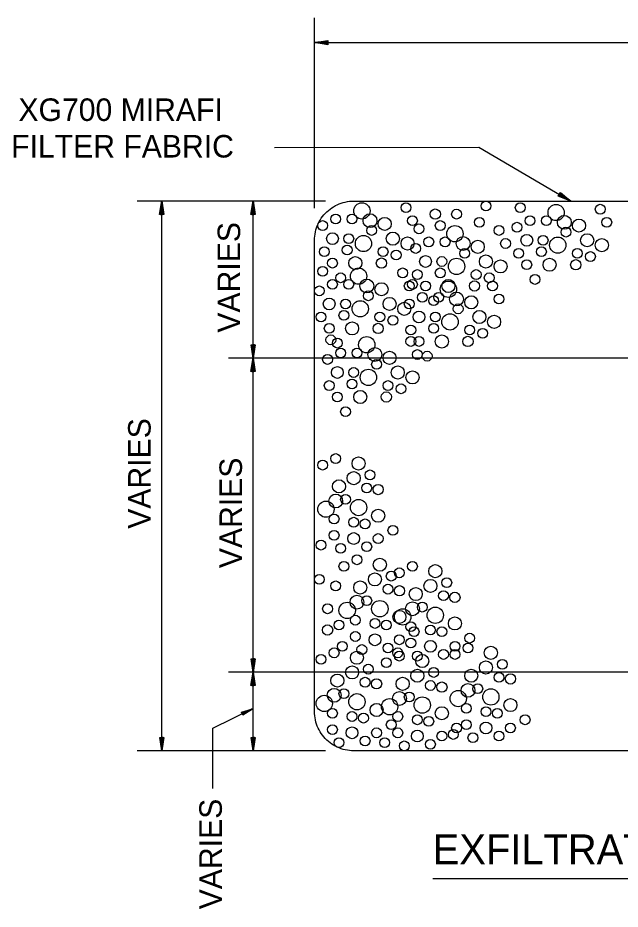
# Model space of a CAD drawing. Extents: x -7.1 to 10, y -5 to 6.
# Drawn here: x 3.602 to 5.369, y -2.41 to 0.206 of the extents above; entities that cross this region are included whole.
import ezdxf

# ---------------------------------------------------------------- set-up
doc = ezdxf.new("R2010")
doc.units = 0
doc.layers.add('Level 11', color=7, linetype='Continuous')
doc.layers.add('Level 6', color=7, linetype='Continuous')

msp = doc.modelspace()

# ---------------------------------------------------------------- linework, layer by layer
at = {"layer": 'Level 11'}
for p, q in [((4.4721, -0.3523), (4.4721, 0.2058)), ((4.4721, 0.1333), (7.2371, 0.1333)), ((4.5041, -0.3319), (3.9515, -0.3319)), ((4.0241, -1.9448), (4.0241, -0.3319)), ((4.292, -0.7927), (4.292, -0.3319)), ((5.6597, -0.7927), (4.2194, -0.7927)), ((4.292, -1.7144), (4.292, -0.7927)), ((5.6597, -1.7144), (4.2194, -1.7144)), ((4.292, -1.9448), (4.292, -1.7144)), ((4.5041, -1.9448), (3.9515, -1.9448)), ((4.8194, -2.3197), (6.9886, -2.3197))]:
    msp.add_line(p, q, dxfattribs=at)
for points in [[(4.3544, -0.1742), (4.9543, -0.1734), (5.2241, -0.3319)], [(4.4748, -0.4223), (4.4763, -0.4163), (4.4781, -0.4103), (4.4803, -0.4045), (4.4827, -0.3987), (4.4855, -0.3931), (4.4886, -0.3877), (4.4919, -0.3824), (4.4956, -0.3774), (4.4995, -0.3725), (4.5036, -0.3679), (4.5081, -0.3635), (4.5127, -0.3593), (4.5176, -0.3554), (4.5226, -0.3518), (4.5279, -0.3484), (4.5333, -0.3453), (4.5389, -0.3425), (4.5446, -0.3401), (4.5505, -0.3379), (4.5565, -0.3361), (4.5625, -0.3346), (4.5686, -0.3334), (4.5748, -0.3326), (4.5811, -0.3321), (4.5873, -0.3319), (4.5873, -0.3319), (6.085, -0.3319)], [(7.1219, -1.9448), (4.5873, -1.9448), (4.5811, -1.9446), (4.5748, -1.9441), (4.5686, -1.9433), (4.5625, -1.9421), (4.5565, -1.9406), (4.5505, -1.9388), (4.5446, -1.9366), (4.5389, -1.9342), (4.5333, -1.9314), (4.5279, -1.9283), (4.5226, -1.925), (4.5176, -1.9213), (4.5127, -1.9174), (4.5081, -1.9133), (4.5036, -1.9088), (4.4995, -1.9042), (4.4956, -1.8993), (4.4919, -1.8943), (4.4886, -1.889), (4.4855, -1.8836), (4.4827, -1.878), (4.4803, -1.8723), (4.4781, -1.8664), (4.4763, -1.8604), (4.4748, -1.8544), (4.4736, -1.8482), (4.4728, -1.8421), (4.4722, -1.8358), (4.4721, -1.8296), (4.4721, -1.8296), (4.4721, -0.4471), (4.4723, -0.4409), (4.4728, -0.4346), (4.4736, -0.4285), (4.4748, -0.4223)], [(4.1735, -2.0552), (4.1736, -1.8784), (4.2894, -1.8219)]]:
    msp.add_lwpolyline(points, dxfattribs=at)
for centre, radius in [((4.611, -0.3606), 0.0239), ((4.7403, -0.3511), 0.0144), ((4.975, -0.3463), 0.0144), ((5.0756, -0.3511), 0.0144), ((4.8265, -0.3702), 0.0151), ((4.8888, -0.3702), 0.0144), ((5.181, -0.3654), 0.0239), ((5.3103, -0.3558), 0.0144), ((4.496, -0.4037), 0.0144), ((4.5343, -0.3846), 0.0144), ((4.5822, -0.3846), 0.0144), ((4.6349, -0.3894), 0.0203), ((4.678, -0.399), 0.0192), ((4.7595, -0.3894), 0.0144), ((4.8409, -0.4037), 0.0144), ((4.9559, -0.3942), 0.0144), ((5.1043, -0.3894), 0.0144), ((5.1522, -0.3894), 0.0144), ((5.2049, -0.3942), 0.0203), ((5.248, -0.4037), 0.0192), ((5.3295, -0.3942), 0.0144), ((4.6397, -0.4181), 0.0144), ((4.7786, -0.4133), 0.0144), ((4.884, -0.4277), 0.024), ((5.0133, -0.4181), 0.0144), ((5.066, -0.4085), 0.0144), ((5.2097, -0.4229), 0.0144), ((4.5248, -0.4421), 0.0173), ((4.5727, -0.4421), 0.0144), ((4.6158, -0.4564), 0.0239), ((4.702, -0.4421), 0.0192), ((4.7451, -0.4564), 0.0192), ((4.8074, -0.4516), 0.0144), ((4.8553, -0.4516), 0.0144), ((4.908, -0.4564), 0.0203), ((5.0325, -0.4564), 0.0144), ((5.0948, -0.4469), 0.0173), ((5.1427, -0.4469), 0.0144), ((5.1858, -0.4612), 0.0239), ((5.272, -0.4469), 0.0192), ((5.3151, -0.4612), 0.0192), ((4.5008, -0.4804), 0.0144), ((4.5679, -0.4756), 0.0144), ((4.6733, -0.4804), 0.0144), ((4.7691, -0.4708), 0.0144), ((4.9511, -0.466), 0.0192), ((5.1379, -0.4804), 0.0144), ((4.5918, -0.5139), 0.0192), ((4.7116, -0.49), 0.0144), ((4.7978, -0.5091), 0.0173), ((4.8457, -0.5091), 0.0144), ((4.9128, -0.4852), 0.0144), ((4.975, -0.5091), 0.0192), ((5.0708, -0.4852), 0.0144), ((5.2433, -0.4852), 0.0144), ((5.2816, -0.4947), 0.0144), ((4.5248, -0.5139), 0.0144), ((4.6685, -0.5139), 0.0151), ((4.8888, -0.5235), 0.024), ((5.0181, -0.5235), 0.0192), ((5.0948, -0.5187), 0.0144), ((5.1618, -0.5187), 0.0192), ((5.2385, -0.5187), 0.0151), ((4.496, -0.5379), 0.0144), ((4.5487, -0.557), 0.0144), ((4.6014, -0.5522), 0.0239), ((4.7307, -0.5426), 0.0144), ((4.7738, -0.5474), 0.0144), ((4.8409, -0.5426), 0.0144), ((4.9463, -0.5474), 0.0144), ((4.9846, -0.557), 0.0144), ((5.1187, -0.5618), 0.0144), ((4.5248, -0.5762), 0.0144), ((4.5727, -0.5762), 0.0144), ((4.6254, -0.581), 0.0203), ((4.6685, -0.5905), 0.0192), ((4.7499, -0.581), 0.0144), ((4.7595, -0.5762), 0.0144), ((4.7978, -0.581), 0.0144), ((4.8649, -0.5905), 0.024), ((4.8649, -0.581), 0.0192), ((4.9415, -0.581), 0.0151), ((4.9942, -0.581), 0.0144), ((4.4865, -0.5953), 0.0144), ((4.6301, -0.6097), 0.0144), ((4.7882, -0.6145), 0.0144), ((4.8361, -0.6145), 0.0144), ((4.8888, -0.6193), 0.0203), ((4.5152, -0.6337), 0.0173), ((4.5631, -0.6337), 0.0144), ((4.6062, -0.648), 0.0239), ((4.6924, -0.6337), 0.0192), ((4.7499, -0.6337), 0.0144), ((4.8217, -0.6241), 0.0144), ((4.9319, -0.6289), 0.0192), ((5.0133, -0.6193), 0.0144), ((4.5583, -0.6672), 0.0144), ((4.7355, -0.648), 0.0192), ((4.8936, -0.648), 0.0144), ((4.9559, -0.672), 0.0192), ((4.4912, -0.672), 0.0144), ((4.6637, -0.672), 0.0144), ((4.702, -0.6816), 0.0144), ((4.7786, -0.672), 0.0173), ((4.8265, -0.672), 0.0144), ((4.8696, -0.6863), 0.024), ((4.999, -0.6863), 0.0192), ((4.5152, -0.7055), 0.0144), ((4.5822, -0.7055), 0.0192), ((4.6589, -0.7055), 0.0151), ((4.7547, -0.7103), 0.0144), ((4.8217, -0.7055), 0.0144), ((4.9271, -0.7103), 0.0144), ((4.9654, -0.7199), 0.0144), ((4.52, -0.739), 0.0144), ((4.6254, -0.7534), 0.0239), ((4.7547, -0.7438), 0.0144), ((4.7786, -0.7438), 0.0144), ((4.8457, -0.7438), 0.0192), ((4.9223, -0.7438), 0.0151), ((4.5391, -0.7486), 0.0144), ((4.5104, -0.7965), 0.0144), ((4.5487, -0.7774), 0.0144), ((4.5966, -0.7774), 0.0144), ((4.6493, -0.7821), 0.0203), ((4.6924, -0.7917), 0.0192), ((4.7738, -0.7821), 0.0144), ((4.8026, -0.7869), 0.0144), ((4.6541, -0.8109), 0.0144), ((4.5391, -0.8348), 0.0173), ((4.587, -0.8348), 0.0144), ((4.6301, -0.8492), 0.0239), ((4.7164, -0.8348), 0.0192), ((4.7595, -0.8492), 0.0192), ((4.5152, -0.8731), 0.0144), ((4.5822, -0.8684), 0.0144), ((4.6876, -0.8731), 0.0144), ((4.6062, -0.9067), 0.0192), ((4.7259, -0.8827), 0.0144), ((4.5391, -0.9067), 0.0144), ((4.6828, -0.9067), 0.0151), ((4.5631, -0.9498), 0.0144), ((4.496, -1.1066), 0.0144), ((4.5343, -1.0874), 0.0144), ((4.6014, -1.1018), 0.0192), ((4.6349, -1.1353), 0.0144), ((4.5439, -1.1689), 0.0192), ((4.587, -1.1449), 0.0192), ((4.6254, -1.1736), 0.0144), ((4.6589, -1.1784), 0.0151), ((4.5343, -1.212), 0.0203), ((4.5631, -1.2072), 0.0144), ((4.5056, -1.2359), 0.0239), ((4.6014, -1.2311), 0.0239), ((4.5296, -1.2647), 0.0144), ((4.6589, -1.2551), 0.0192), ((4.587, -1.2742), 0.0144), ((4.6206, -1.279), 0.0144), ((4.5296, -1.3126), 0.0144), ((4.587, -1.3221), 0.0173), ((4.702, -1.2982), 0.0144), ((4.4912, -1.3413), 0.0144), ((4.6254, -1.3461), 0.0144), ((4.6589, -1.3221), 0.0144), ((4.5487, -1.3509), 0.0144), ((4.5966, -1.3844), 0.0144), ((4.6637, -1.3988), 0.0192), ((4.5583, -1.4036), 0.0144), ((4.7212, -1.4227), 0.0144), ((4.7595, -1.4036), 0.0144), ((4.8265, -1.4179), 0.0192), ((4.4865, -1.4419), 0.0144), ((4.6493, -1.4419), 0.0192), ((4.6972, -1.4323), 0.0144), ((4.8601, -1.4515), 0.0144), ((4.5343, -1.461), 0.0144), ((4.6062, -1.4658), 0.0192), ((4.6876, -1.4706), 0.0144), ((4.7212, -1.4754), 0.0151), ((4.8122, -1.461), 0.0192), ((4.5966, -1.5089), 0.0203), ((4.6254, -1.5041), 0.0144), ((4.7691, -1.485), 0.0192), ((4.8505, -1.4898), 0.0144), ((4.884, -1.4946), 0.0151), ((4.5104, -1.5281), 0.0144), ((4.5679, -1.5329), 0.024), ((4.6637, -1.5281), 0.024), ((4.7595, -1.5281), 0.0203), ((4.7882, -1.5233), 0.0144), ((4.7212, -1.552), 0.0192), ((4.7307, -1.552), 0.024), ((4.8265, -1.5473), 0.024), ((4.5439, -1.576), 0.0144), ((4.5918, -1.5616), 0.0144), ((4.6493, -1.5712), 0.0144), ((4.6828, -1.576), 0.0144), ((4.7547, -1.5808), 0.0144), ((4.884, -1.5712), 0.0192), ((4.5104, -1.5904), 0.0151), ((4.5918, -1.6095), 0.0144), ((4.7643, -1.5952), 0.0144), ((4.8122, -1.5904), 0.0144), ((4.8457, -1.5952), 0.0144), ((4.6493, -1.6191), 0.0173), ((4.7212, -1.6191), 0.0144), ((4.7547, -1.6287), 0.0144), ((4.8122, -1.6383), 0.0173), ((4.9271, -1.6143), 0.0144), ((4.5296, -1.6574), 0.0144), ((4.5535, -1.6383), 0.0144), ((4.611, -1.6478), 0.0144), ((4.6876, -1.6431), 0.0144), ((4.7164, -1.6574), 0.0144), ((4.884, -1.6383), 0.0144), ((4.9223, -1.6431), 0.0144), ((4.9894, -1.6574), 0.0192), ((4.4912, -1.6766), 0.0144), ((4.5966, -1.6718), 0.0192), ((4.6828, -1.6862), 0.0144), ((4.7212, -1.667), 0.0144), ((4.7738, -1.667), 0.0144), ((4.7882, -1.6814), 0.0192), ((4.8505, -1.6622), 0.0144), ((4.884, -1.6622), 0.0144), ((4.5822, -1.7149), 0.0192), ((4.6301, -1.7053), 0.0144), ((4.975, -1.7005), 0.0192), ((5.0229, -1.691), 0.0144), ((4.5391, -1.7389), 0.0192), ((4.7738, -1.7245), 0.0192), ((4.8217, -1.7149), 0.0144), ((4.9319, -1.7245), 0.0192), ((5.0133, -1.7293), 0.0144), ((5.0469, -1.7341), 0.0151), ((4.6206, -1.7436), 0.0144), ((4.6541, -1.7484), 0.0151), ((4.7307, -1.7484), 0.0192), ((4.8122, -1.7532), 0.0144), ((4.8457, -1.758), 0.0151), ((4.9223, -1.7676), 0.0203), ((4.9511, -1.7628), 0.0144), ((4.5296, -1.782), 0.0203), ((4.5583, -1.7772), 0.0144), ((4.5966, -1.8011), 0.0239), ((4.7212, -1.7915), 0.0203), ((4.7499, -1.7868), 0.0144), ((4.8936, -1.7915), 0.0239), ((4.9894, -1.7868), 0.0239), ((4.5008, -1.8059), 0.0239), ((4.6924, -1.8155), 0.0239), ((4.7882, -1.8107), 0.0239), ((5.0469, -1.8107), 0.0192), ((4.5248, -1.8347), 0.0144), ((4.5822, -1.8442), 0.0144), ((4.6541, -1.8251), 0.0192), ((4.7164, -1.8442), 0.0144), ((4.8457, -1.8347), 0.0192), ((4.9175, -1.8203), 0.0144), ((4.975, -1.8299), 0.0144), ((5.0085, -1.8347), 0.0144), ((4.6158, -1.849), 0.0144), ((4.6972, -1.8682), 0.0144), ((4.7738, -1.8538), 0.0144), ((4.8074, -1.8586), 0.0144), ((4.9175, -1.8682), 0.0144), ((5.09, -1.8538), 0.0144), ((4.5248, -1.8826), 0.0144), ((4.5822, -1.8921), 0.0173), ((4.6541, -1.8921), 0.0144), ((4.7164, -1.8921), 0.0144), ((4.8792, -1.8969), 0.0144), ((4.8888, -1.8778), 0.0144), ((4.975, -1.8778), 0.0173), ((5.0469, -1.8778), 0.0144), ((4.5439, -1.9209), 0.0144), ((4.6206, -1.9161), 0.0144), ((4.678, -1.9209), 0.0144), ((4.7738, -1.9017), 0.0173), ((4.8457, -1.9017), 0.0144), ((4.9367, -1.9065), 0.0144), ((5.0133, -1.9017), 0.0144), ((4.7355, -1.9304), 0.0144), ((4.8122, -1.9257), 0.0144)]:
    msp.add_circle(centre, radius, dxfattribs=at)
at = {"layer": 'Level 6'}
for p, q in [((4.5113, 0.1372), (4.4716, 0.1332)), ((4.5113, 0.1268), (4.4716, 0.1333)), ((4.4716, 0.1332), (4.5113, 0.1332)), ((4.5113, 0.1312), (4.4716, 0.1332)), ((4.4716, 0.1332), (4.5113, 0.1292)), ((4.4718, 0.1335), (4.5113, 0.1391)), ((4.5113, 0.1352), (4.4736, 0.1332)), ((4.5113, 0.1391), (4.5113, 0.1268)), ((4.5113, 0.1292), (4.5113, 0.1352)), ((4.5113, 0.1332), (4.5113, 0.1312)), ((5.1873, -0.3171), (5.1935, -0.3065)), ((5.1923, -0.3086), (5.1893, -0.3137)), ((5.1893, -0.3137), (5.2228, -0.3311)), ((5.1903, -0.312), (5.1913, -0.3103)), ((5.2245, -0.3321), (5.1903, -0.312)), ((5.1913, -0.3103), (5.2245, -0.3321)), ((5.2245, -0.3321), (5.1923, -0.3086)), ((5.1935, -0.3065), (5.2244, -0.3322)), ((4.0177, -0.3711), (4.0242, -0.3314)), ((4.024, -0.3314), (4.0201, -0.3711)), ((4.0221, -0.3711), (4.024, -0.3314)), ((4.028, -0.3711), (4.024, -0.3314)), ((4.024, -0.3314), (4.024, -0.3711)), ((4.026, -0.3711), (4.024, -0.3334)), ((4.0243, -0.3316), (4.03, -0.3711)), ((4.2856, -0.3711), (4.2921, -0.3314)), ((4.292, -0.3314), (4.288, -0.3711)), ((4.29, -0.3711), (4.292, -0.3314)), ((4.2959, -0.3711), (4.292, -0.3314)), ((4.292, -0.3314), (4.292, -0.3711)), ((4.294, -0.3711), (4.292, -0.3334)), ((4.2922, -0.3316), (4.2979, -0.3711)), ((5.2242, -0.3322), (5.1873, -0.3171)), ((5.1883, -0.3154), (5.2245, -0.3321)), ((4.03, -0.3711), (4.0177, -0.3711)), ((4.0201, -0.3711), (4.026, -0.3711)), ((4.024, -0.3711), (4.0221, -0.3711)), ((4.2979, -0.3711), (4.2856, -0.3711)), ((4.288, -0.3711), (4.294, -0.3711)), ((4.292, -0.3711), (4.29, -0.3711)), ((4.2918, -0.793), (4.2862, -0.7535)), ((4.2862, -0.7535), (4.2984, -0.7535)), ((4.2881, -0.7536), (4.2921, -0.7932)), ((4.2961, -0.7536), (4.2901, -0.7536)), ((4.2901, -0.7536), (4.2921, -0.7913)), ((4.2984, -0.7535), (4.292, -0.7932)), ((4.2921, -0.7932), (4.2921, -0.7536)), ((4.2921, -0.7536), (4.2941, -0.7536)), ((4.2941, -0.7536), (4.2921, -0.7932)), ((4.2921, -0.7932), (4.2961, -0.7536)), ((4.2856, -0.8319), (4.2921, -0.7923)), ((4.292, -0.7922), (4.288, -0.8319)), ((4.29, -0.8319), (4.292, -0.7922)), ((4.2959, -0.8319), (4.292, -0.7922)), ((4.292, -0.7922), (4.292, -0.8319)), ((4.294, -0.8319), (4.292, -0.7942)), ((4.2922, -0.7924), (4.2979, -0.8319)), ((4.2979, -0.8319), (4.2856, -0.8319)), ((4.288, -0.8319), (4.294, -0.8319)), ((4.292, -0.8319), (4.29, -0.8319)), ((4.2918, -1.7147), (4.2862, -1.6752)), ((4.2862, -1.6752), (4.2984, -1.6752)), ((4.2881, -1.6752), (4.2921, -1.7149)), ((4.2961, -1.6752), (4.2901, -1.6752)), ((4.2901, -1.6752), (4.2921, -1.7129)), ((4.2984, -1.6752), (4.292, -1.7149)), ((4.2921, -1.7149), (4.2921, -1.6752)), ((4.2921, -1.6752), (4.2941, -1.6752)), ((4.2941, -1.6752), (4.2921, -1.7149)), ((4.2921, -1.7149), (4.2961, -1.6752)), ((4.2856, -1.7536), (4.2921, -1.714)), ((4.292, -1.7139), (4.288, -1.7536)), ((4.29, -1.7536), (4.292, -1.7139)), ((4.2959, -1.7536), (4.292, -1.7139)), ((4.292, -1.7139), (4.292, -1.7536)), ((4.294, -1.7536), (4.292, -1.7159)), ((4.2922, -1.7141), (4.2979, -1.7536)), ((4.2979, -1.7536), (4.2856, -1.7536)), ((4.288, -1.7536), (4.294, -1.7536)), ((4.292, -1.7536), (4.29, -1.7536)), ((4.2577, -1.8314), (4.2898, -1.8217)), ((4.2898, -1.8216), (4.2586, -1.8332)), ((4.2593, -1.8346), (4.2898, -1.8216)), ((4.2898, -1.8216), (4.2601, -1.8361)), ((4.2608, -1.8376), (4.2883, -1.8224)), ((4.2615, -1.8391), (4.2898, -1.8216)), ((4.2897, -1.8219), (4.2622, -1.8406)), ((4.2622, -1.8406), (4.2577, -1.8314)), ((4.2586, -1.8332), (4.2608, -1.8376)), ((4.2601, -1.8361), (4.2593, -1.8346)), ((4.0239, -1.9451), (4.0182, -1.9056)), ((4.0182, -1.9056), (4.0305, -1.9056)), ((4.0202, -1.9056), (4.0242, -1.9453)), ((4.0281, -1.9056), (4.0222, -1.9056)), ((4.0222, -1.9056), (4.0242, -1.9433)), ((4.0305, -1.9056), (4.0241, -1.9453)), ((4.0242, -1.9453), (4.0242, -1.9056)), ((4.0242, -1.9056), (4.0262, -1.9056)), ((4.0262, -1.9056), (4.0242, -1.9453)), ((4.0242, -1.9453), (4.0281, -1.9056)), ((4.2918, -1.9451), (4.2862, -1.9056)), ((4.2862, -1.9056), (4.2984, -1.9056)), ((4.2881, -1.9056), (4.2921, -1.9453)), ((4.2961, -1.9056), (4.2901, -1.9056)), ((4.2901, -1.9056), (4.2921, -1.9433)), ((4.2984, -1.9056), (4.292, -1.9453)), ((4.2921, -1.9453), (4.2921, -1.9056)), ((4.2921, -1.9056), (4.2941, -1.9056)), ((4.2941, -1.9056), (4.2921, -1.9453)), ((4.2921, -1.9453), (4.2961, -1.9056))]:
    msp.add_line(p, q, dxfattribs=at)

# ---------------------------------------------------------------- texts
at = {"layer": 'Level 11'}
for s, height, p in [('XG700 MIRAFI', 0.066125, (3.6035, -0.0968)), ('FILTER FABRIC', 0.066125, (3.5822, -0.2041)), ('EXFILTRATION TRENCH SECTION', 0.087469, (4.8189, -2.2777))]:
    msp.add_text(s, height=height, dxfattribs=at).set_placement(p)
for p in [(4.254, -0.7179), (3.9914, -1.2934), (4.2594, -1.4089), (4.2003, -2.4099)]:
    msp.add_text('VARIES', height=0.06613, rotation=90, dxfattribs=at).set_placement(p)

doc.saveas('drawing.dxf')
